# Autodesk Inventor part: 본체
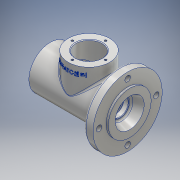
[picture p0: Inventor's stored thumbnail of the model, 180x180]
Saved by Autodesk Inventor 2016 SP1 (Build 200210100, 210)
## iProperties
Created: 2016-08
Part Number: 본체
Material: 알루미늄 6061
Document SubType Name: Modeling
Designer: basic
Density: 2.7 g/cm^3
Appearance: 알루미늄 - 평지
Mass: 763.308 g
Surface Area: 622.667 cm^2
Volume: 282.707 cm^3
Author: basic
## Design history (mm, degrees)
sketch "스케치1"
  geometry: L1 (57.5, 0)-(-57.5, 0); L2 (57.5, 0)-(57.5, 31); L3 (57.5, 31)-(-41.5, 31); L4 (-41.5, 31)-(-41.5, 50); L5 (-41.5, 50)-(-54.5, 50); L6 (-54.5, 50)-(-54.5, 31); L7 (-54.5, 31)-(-57.5, 31); L8 (-57.5, 31)-(-57.5, 0); L9 (57.5, 21)-(48.5, 21); L10 (48.5, 21)-(48.5, 24); L11 (48.5, 24)-(45.5, 24); L12 (45.5, 24)-(45.5, 20); L13 (45.5, 20)-(36.5, 20); L14 (36.5, 20)-(36.5, 17.5); L15 (36.5, 17.5)-(33.25, 17.5); L16 (33.25, 17.5)-(33.25, 18.5); L17 (33.25, 18.5)-(31.5, 18.5); L18 (31.5, 18.5)-(31.5, 17.5); L19 (31.5, 17.5)-(20.5, 17.5); L20 (20.5, 17.5)-(20.5, 26); L21 (20.5, 26)-(-17.5, 26); L22 (-17.5, 26)-(-17.5, 17.5); L23 (-17.5, 17.5)-(-28.5, 17.5); L24 (-28.5, 17.5)-(-28.5, 16.5); L25 (-28.5, 16.5)-(-33.5, 16.5); L26 (-33.5, 16.5)-(-33.5, 10); L27 (-33.5, 10)-(-36.2, 10); L28 (-36.2, 10)-(-36.2, 12.5); L29 (-36.2, 12.5)-(-42.8, 12.5); L30 (-42.8, 12.5)-(-43.5, 12.904); L31 (-43.5, 12.904)-(-43.5, 16); L32 (-43.5, 16)-(-57.5, 21); L33 (1.5, 26)-(1.5, 0); 2 further points
  constraints: 66 end point, 19 perpendicular, 8 vertical, 4 horizontal, 3 point on line, 2 midpoint, 1 coincident
  dimensions: "d0" = 115 distance of L1.start L1.end; "d1" = 100 diameter of L5 L1; "d2" = 62 diameter of L7 L1; "d3" = 13 distance of L4.end L5.end; "d4" = 3 distance of L6.end L7.end; "d5" = 62 diameter of L3 L1; "d6" = 3 distance of L10.end L11.end; "d7" = 40 diameter of L13 L1; "d9" = 12 distance between parallel lines of L2 L12; "d10" = 21 distance between parallel lines of L2 L14; "d11" = 42 diameter of L9 L1; "d12" = 48 diameter of L11 L1; "d13" = 26 distance from line of L1.start L18; "d14" = 35 diameter of L15 L1; "d15" = 35 diameter of L19 L1; "d16" = 1.75 distance of L16.end L17.end; "d17" = 37 diameter of L17 L1; "d18" = 52 diameter of L21 L1; "d19" = 38 distance of L20.end L21.end; "d41" = 60 distance between parallel lines of L18 L24; "d42" = 33 diameter of L25 L1; "d43" = 35 diameter of L23 L1; "d44" = 5 distance of L24.end L25.end; "d45" = 2.7 distance of L26.end L27.end; "d46" = 20 diameter of L27 L1; "d47" = 25 diameter of L29 L1; "d54" = 0.7 horizontal distance of L29.end L30.end; "d55" = 30 deg angle of L29 L30; "d56" = 32 diameter of L31.end L1; "d57" = 42 diameter of L32.end L1; "d58" = 7.3 distance between parallel lines of L31 L28; "d76" = 56 distance between parallel lines of L2 L33
revolve "회전1" sketch "스케치1" stored, may be unused: angle "d59" = 90 deg
node "작업 평면1"
sketch "스케치2"
  geometry: L1 (-57.5, 31)-(-57.5, -31) reference; C1 r 30 at (-1.5, 0); 1 further point
  constraints: 1 centre point, 1 horizontal alignment, 1 midpoint
  dimensions: "d61" = 60 diameter of C1; "d75" = 56 distance from line of C1.centre L1
extrude "돌출1" join sketch "스케치2" stored distance "d62" = 10; taper "d63" = 0 deg; dims "d88" = 41.5
hole "구멍1" diameter "d66" = 38; stored, may be unused: countersink angle "d70" = 90 deg, drill point angle "d72" = 0 deg; dims "d64" = 10, "d65" = 10, "d67" = 6, "d68" = 4, "d69" = 2, "d71" = 8
feature "스레드1" dims "d73" = 10, "d74" = 0
sketch "스케치4"
  geometry: L1 (0, 0)-(0, 24); C1 r 30 at (0, 0) reference; 2 further points
  constraints: 2 end point, 1 coincident, 1 vertical
  dimensions: "d77" = 24 distance of L1.start L1.end
hole "구멍2" sketch "스케치4" at (0, 24) diameter "d78" = 3.242; stored, may be unused: countersink angle "d82" = 90 deg, drill point angle "d84" = 118 deg; dims "d79" = 8, "d80" = 4, "d81" = 2, "d83" = 10
sketch "스케치5"
  geometry: L1 (0, 0)-(-41.5, 0); 1 further point
  constraints: 2 end point, 1 coincident, 1 horizontal
  dimensions: "d88" = 41.5 distance of L1.start L1.end
hole "구멍3" sketch "스케치5" at (-41.5, 0) diameter "d89" = 8; stored, may be unused: countersink angle "d93" = 90 deg, drill point angle "d95" = 0 deg; dims "d90" = 8, "d91" = 4, "d92" = 2, "d94" = 10
node "작업 평면2"
sketch "스케치6"
  geometry: L1 (-31.5, 49)-(28.5, 49) reference; L2 (-57.5, 31)-(-57.5, -31) reference; 2 further points
  constraints: 1 other
  dimensions: "d100" = 10 distance from line of L1 point (-1.5, 39); "d101" = 56 distance from line of L2 point (-1.5, 39)
feature "엠보싱1" sketch "스케치6" dims "d102" = 0.5, "d103" = 0
fillet "모깎기1" dims "d104" = 3
fillet "모깎기2" dims "d105" = 3
fillet "모깎기3" dims "d106" = 3
fillet "모깎기4" dims "d107" = 3
fillet "모깎기5" dims "d108" = 0.3
fillet "모깎기6" dims "d109" = 3
fillet "모깎기7" dims "d110" = 3
fillet "모깎기8" dims "d111" = 0.3
chamfer "모따기1" distance "d112" = 1; stored, may be unused: second distance "d113" = 2, angle "d114" = 45 deg
node "솔리드1"
pattern_circular "원형 패턴1" dims angle "d86" = 360 deg
pattern_circular "원형 패턴2" dims angle "d97" = 360 deg
other parameters: "d60" = 49, "d99" = -31
